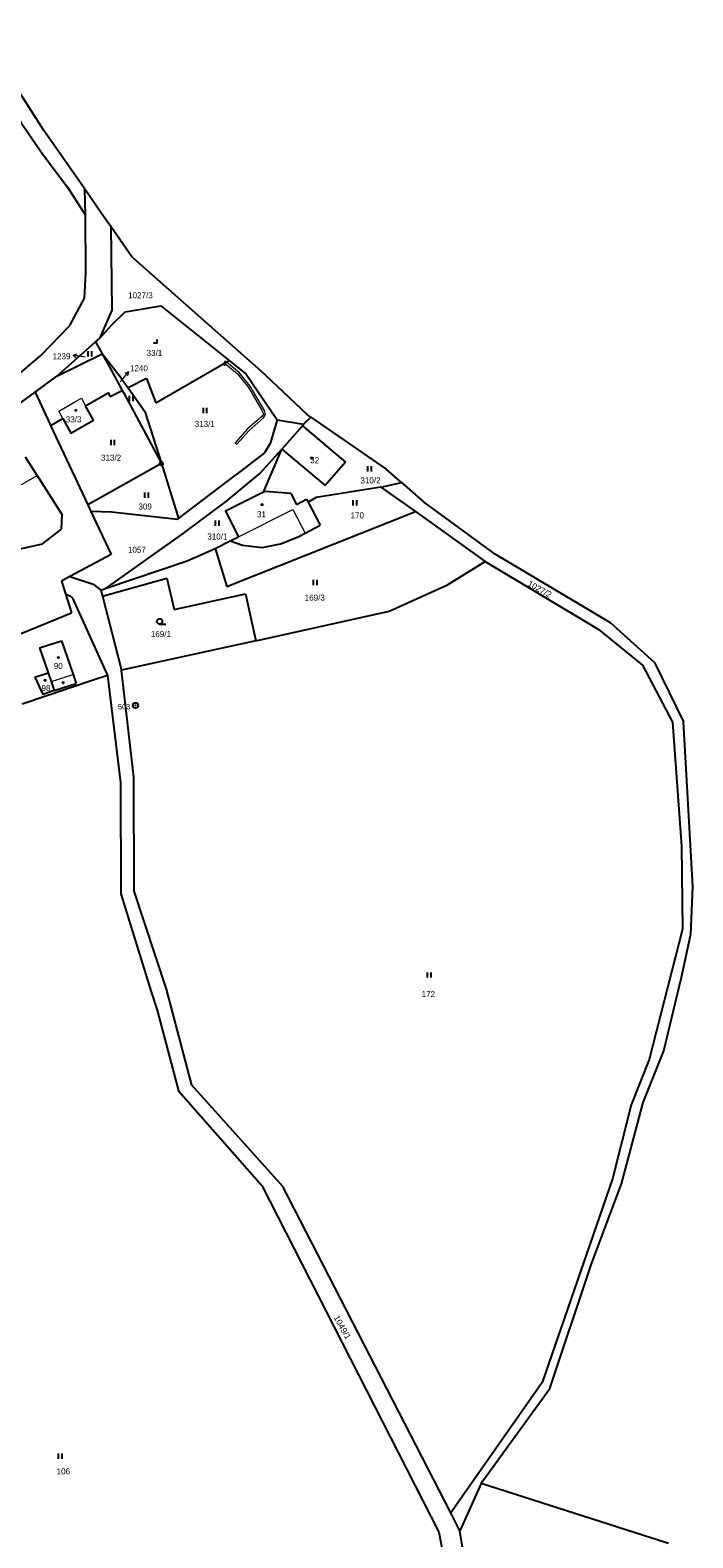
# Model space of a CAD drawing. Extents: x -744132 to -742433, y -984679 to -982287.
# Drawn here: x -742804.5 to -742617.6, y -984255 to -983829.9 of the extents above; entities that cross this region are included whole.
import ezdxf
from ezdxf.enums import TextEntityAlignment as Align

# ---------------------------------------------------------------- set-up
doc = ezdxf.new("R2010")
doc.units = 0
doc.header["$LTSCALE"] = 0.68
for name, color, linetype, lineweight in [('1', 7, 'Continuous', 25), ('13', 7, 'Continuous', 13), ('3', 7, 'Continuous', 25), ('4', 7, 'Continuous', 13), ('5', 7, 'Continuous', 25), ('7', 7, 'Continuous', 13), ('8', 7, 'Continuous', 25)]:
    doc.layers.add(name, color=color, linetype=linetype, lineweight=lineweight)
doc.layers.add('2', color=7, linetype='Continuous')

msp = doc.modelspace()

# ---------------------------------------------------------------- linework, layer by layer
at = {"layer": '1'}
for p, q in [((-742800.89, -983865.04), (-742793.94, -983874.19)), ((-742789.1, -983874.77), (-742790.13, -983873.29)), ((-742793.94, -983874.19), (-742788.91, -983882.12)), ((-742783.51, -983882.81), (-742789.1, -983874.77)), ((-742788.91, -983882.12), (-742789.1, -983874.77)), ((-742788.82, -983898.38), (-742788.91, -983882.12)), ((-742781.77, -983885.31), (-742783.51, -983882.81)), ((-742775.82, -983893.85), (-742781.77, -983885.31)), ((-742781.77, -983885.31), (-742781.48, -983908.85)), ((-742740.22, -983925.3), (-742775.82, -983893.85)), ((-742789.21, -983905.45), (-742788.82, -983898.38)), ((-742793.35, -983913.21), (-742789.21, -983905.45)), ((-742777.75, -983909.38), (-742767.67, -983907.68)), ((-742767.67, -983907.68), (-742748.39, -983923.09)), ((-742781.48, -983908.85), (-742784.96, -983916.85)), ((-742781.46, -983913.03), (-742777.75, -983909.38)), ((-742801.5, -983921.65), (-742793.35, -983913.21)), ((-742784.96, -983916.85), (-742781.46, -983913.03)), ((-742797.01, -983927.52), (-742786.05, -983917.81)), ((-742786.05, -983917.81), (-742784.96, -983916.85)), ((-742786.05, -983917.81), (-742784.16, -983921.21)), ((-742816.35, -983934.19), (-742801.5, -983921.65)), ((-742797.01, -983927.52), (-742784.16, -983921.21)), ((-742784.16, -983921.21), (-742781.35, -983926.26)), ((-742778.84, -983928.03), (-742784.16, -983921.21)), ((-742769.11, -983935.02), (-742748.39, -983923.09)), ((-742748.39, -983923.09), (-742743.56, -983926.95)), ((-742803.12, -983932.02), (-742797.01, -983927.52)), ((-742781.35, -983926.26), (-742778.53, -983931.53)), ((-742778.84, -983928.03), (-742776.92, -983930.73)), ((-742771.75, -983928.16), (-742776.92, -983930.73)), ((-742771.75, -983928.16), (-742769.11, -983935.02)), ((-742743.56, -983926.95), (-742734.85, -983939.77)), ((-742738.09, -983927.31), (-742740.22, -983925.3)), ((-742726.2, -983938.51), (-742738.09, -983927.31)), ((-742807.62, -983935.3), (-742803.12, -983932.02)), ((-742803.12, -983932.02), (-742798.96, -983940.95)), ((-742778.53, -983931.53), (-742778.12, -983932.31)), ((-742778.12, -983932.31), (-742767.52, -983952.14)), ((-742776.92, -983930.73), (-742772.15, -983937.41)), ((-742772.15, -983937.41), (-742767.52, -983952.14)), ((-742798.96, -983940.95), (-742798.79, -983941.36)), ((-742798.79, -983941.36), (-742795.3, -983939.41)), ((-742798.79, -983941.36), (-742788.25, -983963.71)), ((-742734.85, -983939.77), (-742736.79, -983946.51)), ((-742734.85, -983939.77), (-742727.42, -983941.05)), ((-742727.76, -983941.45), (-742733.51, -983948.07)), ((-742727.42, -983941.05), (-742727.76, -983941.45)), ((-742727.76, -983941.45), (-742715.62, -983951.72)), ((-742727.42, -983941.05), (-742725.4, -983939.06)), ((-742725.4, -983939.06), (-742726.2, -983938.51)), ((-742725.4, -983939.06), (-742704.16, -983953.74)), ((-742802.53, -983955.53), (-742805.85, -983950.36)), ((-742738.46, -983949.14), (-742746.2, -983955.11)), ((-742739.77, -983954.91), (-742733.51, -983948.07)), ((-742738.75, -983960.22), (-742733.51, -983948.07)), ((-742736.79, -983946.51), (-742738.46, -983949.14)), ((-742733.51, -983948.07), (-742721.36, -983958.34)), ((-742767.52, -983952.14), (-742788.25, -983963.71)), ((-742767.52, -983952.14), (-742762.65, -983967.63)), ((-742715.62, -983951.72), (-742721.36, -983958.34)), ((-742699.81, -983957.49), (-742704.16, -983953.74)), ((-742802.53, -983955.53), (-742795.47, -983966.53)), ((-742762.65, -983967.63), (-742746.2, -983955.11)), ((-742749.1, -983962.7), (-742739.77, -983954.91)), ((-742705.64, -983958.73), (-742723.82, -983961.68)), ((-742705.64, -983958.73), (-742699.81, -983957.49)), ((-742705.64, -983958.73), (-742695.86, -983965.66)), ((-742699.81, -983957.49), (-742693.7, -983962.77)), ((-742761.39, -983971.85), (-742749.1, -983962.7)), ((-742731.01, -983960.54), (-742729.41, -983963.65)), ((-742729.41, -983963.65), (-742726.56, -983962.12)), ((-742726.56, -983962.12), (-742726.13, -983962.96)), ((-742723.82, -983961.68), (-742726.13, -983962.96)), ((-742726.13, -983962.96), (-742722.77, -983969.46)), ((-742673.34, -983977.66), (-742693.7, -983962.77)), ((-742795.63, -983970.61), (-742795.47, -983966.53)), ((-742788.25, -983963.71), (-742787.36, -983965.6)), ((-742787.36, -983965.6), (-742781.64, -983977.76)), ((-742781.54, -983965.78), (-742787.36, -983965.6)), ((-742762.96, -983967.87), (-742781.54, -983965.78)), ((-742749.05, -983986.76), (-742695.86, -983965.66)), ((-742695.86, -983965.66), (-742676.16, -983979.74)), ((-742801.02, -983974.74), (-742795.63, -983970.61)), ((-742762.96, -983967.87), (-742762.65, -983967.63)), ((-742726.99, -983971.73), (-742722.77, -983969.46)), ((-742811.46, -983977.13), (-742801.02, -983974.74)), ((-742783.1, -983987.28), (-742761.39, -983971.85)), ((-742752.38, -983976.11), (-742748.07, -983973.95)), ((-742748.07, -983973.95), (-742745.76, -983972.79)), ((-742748.07, -983973.95), (-742744.66, -983975.12)), ((-742744.66, -983975.12), (-742739.13, -983975.81)), ((-742739.13, -983975.81), (-742733.94, -983974.76)), ((-742733.94, -983974.76), (-742728.9, -983972.76)), ((-742728.9, -983972.76), (-742726.99, -983971.73)), ((-742781.64, -983977.76), (-742793.32, -983983.98)), ((-742783.1, -983987.28), (-742760.28, -983979.53)), ((-742760.28, -983979.53), (-742752.38, -983976.11)), ((-742752.38, -983976.11), (-742749.05, -983986.76)), ((-742686.87, -983986.32), (-742676.16, -983979.74)), ((-742676.16, -983979.74), (-742644.33, -983998.8)), ((-742640.83, -983997), (-742673.34, -983977.66)), ((-742793.32, -983983.98), (-742795.69, -983985.24)), ((-742793.32, -983983.98), (-742786.74, -983986.14)), ((-742795.69, -983985.24), (-742794.55, -983988.84)), ((-742786.74, -983986.14), (-742784.62, -983987.8)), ((-742784.62, -983987.8), (-742783.1, -983987.28)), ((-742784.62, -983987.8), (-742784.11, -983989.55)), ((-742784.11, -983989.55), (-742766.01, -983984.46)), ((-742766.01, -983984.46), (-742763.88, -983993.23)), ((-742703.23, -983993.78), (-742686.87, -983986.32)), ((-742794.55, -983988.84), (-742793.32, -983989.38)), ((-742794.55, -983988.84), (-742792.81, -983994.21)), ((-742793.32, -983989.38), (-742792.53, -983990.05)), ((-742792.53, -983990.05), (-742787.22, -984001.89)), ((-742784.11, -983989.55), (-742778.71, -984010.36)), ((-742763.88, -983993.23), (-742743.77, -983988.83)), ((-742743.77, -983988.83), (-742740.89, -984002.14)), ((-742812.62, -984002.25), (-742792.81, -983994.21)), ((-742740.89, -984002.14), (-742703.23, -983993.78)), ((-742628.5, -984008.17), (-742640.83, -983997)), ((-742644.33, -983998.8), (-742631.84, -984008.98)), ((-742801.85, -984004.06), (-742795.67, -984002.12)), ((-742801.85, -984004.06), (-742799.41, -984011.16)), ((-742795.67, -984002.12), (-742792.41, -984011.61)), ((-742787.22, -984001.89), (-742782.7, -984011.86)), ((-742740.89, -984002.14), (-742778.71, -984010.36)), ((-742631.84, -984008.98), (-742623.41, -984025.06)), ((-742628.5, -984008.17), (-742620.24, -984024.92)), ((-742786.48, -984013.12), (-742806.72, -984019.96)), ((-742803.18, -984012.34), (-742799.41, -984011.16)), ((-742803.18, -984012.34), (-742800.9, -984017.2)), ((-742799.41, -984011.16), (-742798.59, -984013.56)), ((-742798.59, -984013.56), (-742797.72, -984016.08)), ((-742797.72, -984016.08), (-742791.54, -984014.15)), ((-742792.41, -984011.61), (-742791.54, -984014.15)), ((-742782.7, -984011.86), (-742786.48, -984013.12)), ((-742782.7, -984011.86), (-742779.02, -984042.01)), ((-742775.24, -984040.55), (-742778.71, -984010.36)), ((-742797.72, -984016.08), (-742800.9, -984017.2)), ((-742623.41, -984025.06), (-742620.85, -984059.98)), ((-742617.64, -984071.33), (-742620.24, -984024.92)), ((-742779.02, -984042.01), (-742778.93, -984073.46)), ((-742775.23, -984072.65), (-742775.24, -984040.55)), ((-742620.85, -984059.98), (-742620.53, -984083.44)), ((-742778.93, -984073.46), (-742770.38, -984101.1)), ((-742766.08, -984100.32), (-742775.23, -984072.65)), ((-742618.2, -984084.77), (-742617.64, -984071.33)), ((-742620.53, -984083.44), (-742629.99, -984120.16)), ((-742620.8, -984096.9), (-742618.2, -984084.77)), ((-742625.83, -984117.72), (-742620.8, -984096.9)), ((-742770.38, -984101.1), (-742768.73, -984106.28)), ((-742758.9, -984127.34), (-742766.08, -984100.32)), ((-742768.73, -984106.28), (-742762.72, -984128.99)), ((-742629.99, -984120.16), (-742635.04, -984132.97)), ((-742631.61, -984132.27), (-742625.83, -984117.72)), ((-742733.3, -984155.93), (-742758.9, -984127.34)), ((-742762.72, -984128.99), (-742739.2, -984155.7)), ((-742635.04, -984132.97), (-742640.29, -984153.83)), ((-742637.76, -984155.22), (-742631.61, -984132.27)), ((-742640.29, -984153.83), (-742660.11, -984211.23)), ((-742739.2, -984155.7), (-742689.26, -984253.42)), ((-742685.84, -984248), (-742733.3, -984155.93)), ((-742646.25, -984177.8), (-742637.76, -984155.22)), ((-742657.98, -984212.88), (-742646.25, -984177.8)), ((-742660.11, -984211.23), (-742685.84, -984248)), ((-742676.84, -984238.93), (-742657.98, -984212.88)), ((-742677.37, -984239.66), (-742676.84, -984238.93)), ((-742677.37, -984239.66), (-742683.36, -984253.03)), ((-742624.53, -984256.61), (-742677.37, -984239.66)), ((-742683.36, -984253.03), (-742685.84, -984248)), ((-742689.26, -984253.42), (-742680.62, -984297.71)), ((-742681.71, -984262.69), (-742683.36, -984253.03))]:
    msp.add_line(p, q, dxfattribs=at)
for points in [[(-742790.13, -983873.29), (-742800.65, -983858.18), (-742818.84, -983829.92)], [(-742814.87, -983843.28), (-742807.06, -983856.08), (-742800.89, -983865.04)], [(-742788.87, -983935.81), (-742782.54, -983932.21), (-742781.94, -983933.23), (-742778.53, -983931.53)], [(-742795.3, -983939.41), (-742793.05, -983943.54), (-742786.67, -983939.92), (-742788.87, -983935.81)], [(-742738.75, -983960.22), (-742749.39, -983965.54), (-742745.76, -983972.79)], [(-742731.01, -983960.54), (-742738.23, -983959.96), (-742738.75, -983960.22)]]:
    msp.add_lwpolyline(points, dxfattribs=at)
at = {"layer": '13'}
msp.add_lwpolyline([(-742749.37, -983924.13), (-742746.03, -983926.85), (-742742.98, -983930.64), (-742738.96, -983937.41), (-742738.75, -983938.19), (-742739.14, -983938.86), (-742743.2, -983942.36), (-742746.66, -983946.23), (-742746.21, -983946.63), (-742742.78, -983942.79), (-742738.67, -983939.25), (-742738.11, -983938.28), (-742738.4, -983937.17), (-742742.49, -983930.3), (-742745.6, -983926.43), (-742749.16, -983923.53), (-742749.49, -983923.26), (-742750.1, -983924.08), (-742749.64, -983924.44)], close=True, dxfattribs=at)
at = {"layer": '3'}
for p, q in [((-742788.161, -983921.9), (-742788.161, -983920.4)), ((-742787.16, -983921.9), (-742787.16, -983920.4)), ((-742776.501, -983934.55), (-742776.501, -983933.05)), ((-742775.5, -983934.55), (-742775.5, -983933.05)), ((-742755.671, -983937.87), (-742755.671, -983936.37)), ((-742754.67, -983937.87), (-742754.67, -983936.37)), ((-742781.711, -983946.95), (-742781.711, -983945.45)), ((-742780.71, -983946.95), (-742780.71, -983945.45)), ((-742709.301, -983954.39), (-742709.301, -983952.89)), ((-742708.3, -983954.39), (-742708.3, -983952.89)), ((-742772.151, -983961.78), (-742772.151, -983960.28)), ((-742771.15, -983961.78), (-742771.15, -983960.28)), ((-742713.381, -983963.92), (-742713.381, -983962.42)), ((-742712.38, -983963.92), (-742712.38, -983962.42)), ((-742752.231, -983969.65), (-742752.231, -983968.15)), ((-742751.23, -983969.65), (-742751.23, -983968.15)), ((-742724.571, -983986.37), (-742724.571, -983984.87)), ((-742723.57, -983986.37), (-742723.57, -983984.87)), ((-742768.003, -983997.36), (-742766.253, -983997.36)), ((-742692.451, -984097.07), (-742692.451, -984095.57)), ((-742691.45, -984097.07), (-742691.45, -984095.57)), ((-742796.511, -984232.73), (-742796.511, -984231.23)), ((-742795.51, -984232.73), (-742795.51, -984231.23))]:
    msp.add_line(p, q, dxfattribs=at)
msp.add_lwpolyline([(-742769.691, -983918.11), (-742768.69, -983918.11), (-742768.69, -983917.11)], dxfattribs=at)
msp.add_circle((-742768.0029, -983996.6098), 0.75, dxfattribs=at)
at = {"layer": '4'}
for p, q in [((-742808.73, -983959.04), (-742802.53, -983955.53)), ((-742745.76, -983972.79), (-742730.41, -983965.11)), ((-742730.41, -983965.11), (-742726.99, -983971.73)), ((-742798.59, -984013.56), (-742792.41, -984011.61))]:
    msp.add_line(p, q, dxfattribs=at)
msp.add_lwpolyline([(-742795.3, -983939.41), (-742796.43, -983937.32), (-742791.77, -983934.65), (-742790.03, -983933.66), (-742788.87, -983935.81)], dxfattribs=at)
at = {"layer": '5'}
for centre in [(-742791.6468, -983937.1192), (-742725.1068, -983950.5692), (-742739.1068, -983963.6892), (-742796.5768, -984006.7992), (-742800.3368, -984013.2392), (-742795.1968, -984013.9192)]:
    msp.add_circle(centre, 0.175, dxfattribs=at)
at = {"layer": '7'}
for p, q in [((-742792.395, -983921.539), (-742791.496, -983922.206)), ((-742776.811, -983926.248), (-742777.831, -983926.711))]:
    msp.add_line(p, q, dxfattribs=at)
for points in [[(-742789, -983922.14), (-742789.44, -983922.06), (-742792.395, -983921.539), (-742791.322, -983921.22)], [(-742779.13, -983929.11), (-742778.7, -983928.58), (-742776.811, -983926.248), (-742777.053, -983927.341)]]:
    msp.add_lwpolyline(points, dxfattribs=at)
at = {"layer": '8'}
for centre, radius in [((-742767.52, -983952.1399), 0.5), ((-742767.52, -983952.1399), 0.0303), ((-742774.8, -984020.2998), 0.75), ((-742774.8, -984020.2998), 0.03)]:
    msp.add_circle(centre, radius, dxfattribs=at)

# ---------------------------------------------------------------- texts
at = {"layer": '2'}
for s, p in [('1027/3', (-742776.89, -983905.525)), ('33/1', (-742771.68, -983921.775)), ('1240', (-742776.36, -983926.075)), ('33/3', (-742794.47, -983940.505)), ('313/1', (-742758.12, -983941.785)), ('313/2', (-742784.53, -983951.315)), ('32', (-742725.54, -983952.015)), ('310/2', (-742711.38, -983957.715)), ('309', (-742773.98, -983965.085)), ('31', (-742740.55, -983967.245)), ('170', (-742714.17, -983967.565)), ('1057', (-742776.94, -983977.275)), ('310/1', (-742754.56, -983973.535)), ('169/3', (-742727.1, -983990.765)), ('169/1', (-742770.49, -984001.055)), ('90', (-742797.84, -984010.035)), ('98', (-742801.32, -984016.265)), ('172', (-742694.12, -984102.535)), ('106', (-742797.05, -984237.125))]:
    msp.add_text(s, height=1.7, dxfattribs=at).set_placement(p)
msp.add_text('1239', height=1.7, dxfattribs=at).set_placement((-742793.14, -983922.712), align=Align.RIGHT)
at = {"layer": '2', "width": 1.05}
for s, rotation, p in [('1027/2', 331, (-742664.436, -983986.491)), ('1049/1', 299, (-742718.971, -984192.866))]:
    msp.add_text(s, height=1.7, rotation=rotation, dxfattribs=at).set_placement(p)
at = {"layer": '8'}
msp.add_text('503', height=1.5, dxfattribs=at).set_placement((-742776.299, -984021.417), align=Align.RIGHT)

doc.saveas('drawing.dxf')
